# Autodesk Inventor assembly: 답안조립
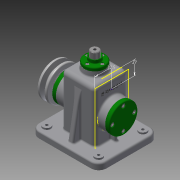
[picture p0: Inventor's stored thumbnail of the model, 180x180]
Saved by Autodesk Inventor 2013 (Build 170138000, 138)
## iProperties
Created: 2016-01
Part Number: 답안조립
Document SubType Name: Assembly
Designer: Administrator
Author: Administrator
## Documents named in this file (19)
- C:\Users\Administrator\Desktop\460127v1019\답안조립.iam
- C:\Users\Administrator\Desktop\460127v1019\1본체.ipt
- C:\Users\Administrator\Desktop\460127v1019\V-벨트풀리.ipt
- C:\Users\Administrator\Desktop\460127v1019\고정핀.ipt
- C:\Users\Administrator\Desktop\460127v1019\뒤커버.ipt
- C:\Users\Administrator\Desktop\460127v1019\링크.ipt
- C:\Users\Administrator\Desktop\460127v1019\멈춤링 6 x 5.ipt
- C:\Users\Administrator\Desktop\460127v1019\멈춤링 15 x 1.ipt
- C:\Users\Administrator\Desktop\460127v1019\베어링 15 x 35 x 11.ipt
- C:\Users\Administrator\Desktop\460127v1019\볼트 M3 x 8.ipt
- C:\Users\Administrator\Desktop\460127v1019\볼트 M4 x 10.ipt
- C:\Users\Administrator\Desktop\460127v1019\볼트 M6 x 12.ipt
- C:\Users\Administrator\Desktop\460127v1019\상부부시.ipt
- C:\Users\Administrator\Desktop\460127v1019\슬라이드바.ipt
- C:\Users\Administrator\Desktop\460127v1019\앞커버.ipt
- C:\Users\Administrator\Desktop\460127v1019\오일실 15 25 7.ipt
- C:\Users\Administrator\Desktop\460127v1019\와셔.ipt
- C:\Users\Administrator\Desktop\460127v1019\키 5 x 5 x 14.ipt
- C:\Users\Administrator\Desktop\460127v1019\편심축.ipt
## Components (16 placed, 6 different names)
1. 1본체:1
2. V-벨트풀리:1 — 각도:2
3. 고정핀:1
4. ISO 4018 M6 x 12:1
5. ISO 4762 M4 x 10:1
6. ISO 4762 M4 x 10:3
7. ISO 4762 M4 x 10:4
8. ISO 4762 M4 x 10:5
9. ISO 4762 M4 x 10:2
10. ISO 4762 M4 x 10:6
11. ISO 4762 M4 x 10:7
12. ISO 4762 M4 x 10:8
13. ISO 4762 M3 x 8:1
14. ISO 4762 M3 x 8:2
15. ISO 4762 M3 x 8:3
16. ISO 4762 M3 x 8:4
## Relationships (1: Angle 1)
- 각도:2 [Angle]: V-벨트풀리:1
